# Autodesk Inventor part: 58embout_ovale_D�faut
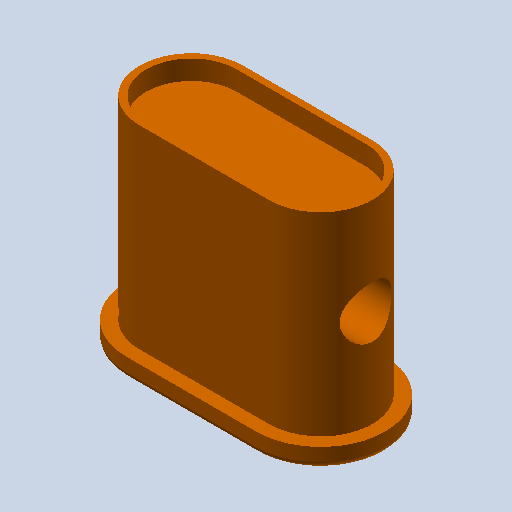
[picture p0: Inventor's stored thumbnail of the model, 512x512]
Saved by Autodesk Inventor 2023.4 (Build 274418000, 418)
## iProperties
Created: 2011-01
Part Number: 58embout_ovale_D�faut
Document SubType Name: Modeling
Designer: eric
Density: 1 g/cm^3
Mass: 14.6669 g
Surface Area: 54.2555 cm^2
Volume: 14.6669 cm^3
Material: Générique
Appearance: 255,128,0_1
Author: eric
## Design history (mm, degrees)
feature "Base1"
node "Corps solides"
node "Corps surfaciques"
node "Solide1"
